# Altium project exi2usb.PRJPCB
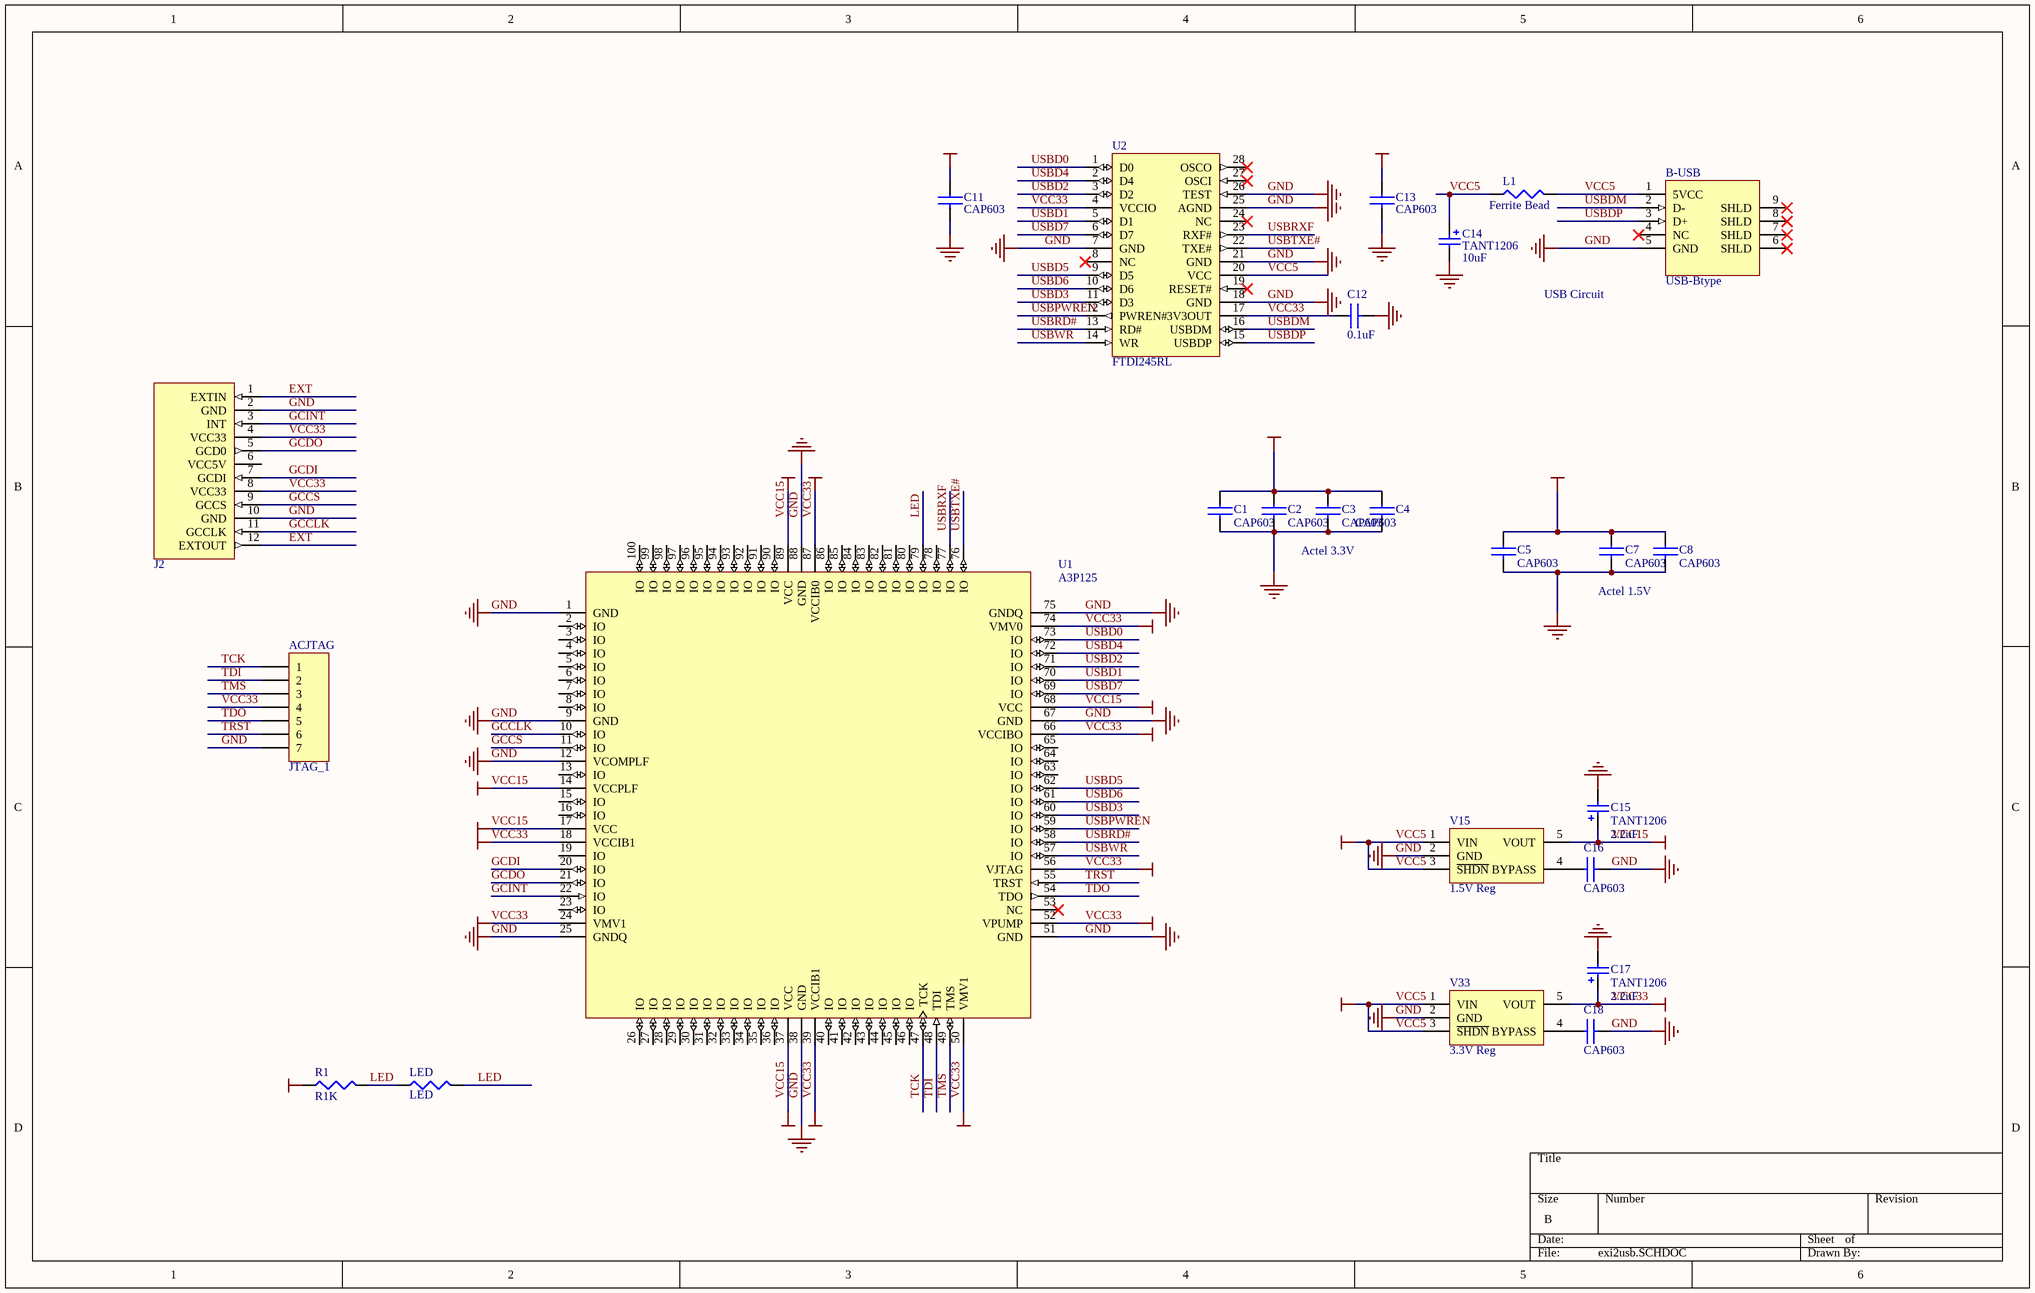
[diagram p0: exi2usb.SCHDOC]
1 sheet, 25 parts. Net scope: global (net labels, ports and power ports of the same name join across sheets).
Board file: exi2usb.PCBDOC

## Sheet exi2usb.SCHDOC
size B

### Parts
ACJTAG  JTAG_1  [ACTJTAG]
B-USB  USB-Btype  [Mini-USB-SMT]
C1  CAP603  [CAP0603]
C2  CAP603  [CAP0603]
C3  CAP603  [CAP0603]
C4  CAP603  [CAP0603]
C5  CAP603  [CAP0603]
C7  CAP603  [CAP0603]
C8  CAP603  [CAP0603]
C11  CAP603  [CAP0603]
C12  0.1uF  [CAP0603]
C13  CAP603  [CAP0603]
C14  TANT1206  value 10uF  [CAP1206]
C15  TANT1206  value 2.2uF  [CAP1206]
C16  CAP603  [CAP0603]
C17  TANT1206  value 2.2uF  [CAP1206]
C18  CAP603  [CAP0603]
J2  GCMEMPADS  [GCMEMPADS]  (value not drawn)
L1  Ferrite Bead  [RES0805]
LED  LED  [RES0805]
R1  R1K  [RES0805]
U1  A3P125  [ACTELVQ100]
U2  FTDI245RL  [SSO-G28/X.4]
V15  1.5V Reg  [SO-G5/P.95]
V33  3.3V Reg  [SO-G5/P.95]

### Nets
GND: ACJTAG.7 B-USB.5(GND) C1.2 C2.2 C3.2 C4.2 C5.2 C7.2 C8.2 C11.2 C12.2 C13.2 C14.2 C15.2 C16.2 C17.2 C18.2 J2.2(GND) J2.10(GND) U1.1(GND) U1.9(GND) U1.12(VCOMPLF) U1.25(GNDQ) U1.38(GND) U1.51(GND) U1.67(GND) U1.75(GNDQ) U1.88(GND) U2.7(GND) U2.18(GND) U2.21(GND) U2.25(AGND) U2.26(TEST) V15.2(GND) V33.2(GND)
VCC5: B-USB.1(5VCC) C13.1 C14.1 L1.1 L1.2 U2.20(VCC) V15.1(VIN) V15.3(~{SHDN}) V33.1(VIN) V33.3(~{SHDN})
VCC15: C5.1 C7.1 C8.1 C15.1 U1.14(VCCPLF) U1.17(VCC) U1.37(VCC) U1.68(VCC) U1.89(VCC) V15.5(VOUT)
VCC33: ACJTAG.4 C1.1 C2.1 C3.1 C4.1 C11.1 C12.1 C17.1 J2.4(VCC33) J2.8(VCC33) R1.1 U1.18(VCCIB1) U1.24(VMV1) U1.39(VCCIB1) U1.50(VMV1) U1.52(VPUMP) U1.56(VJTAG) U1.66(VCCIBO) U1.74(VMV0) U1.87(VCCIB0) U2.4(VCCIO) U2.17(3V3OUT) V33.5(VOUT)
EXT: J2.1(EXTIN) J2.12(EXTOUT)
GCCLK: J2.11(GCCLK) U1.10(IO)
GCCS: J2.9(GCCS) U1.11(IO)
GCDI: J2.7(GCDI) U1.20(IO)
GCDO: J2.5(GCD0) U1.21(IO)
GCINT: J2.3(INT) U1.22(IO)
LED: LED.1 LED.2 R1.2 U1.79(IO)
TCK: ACJTAG.1 U1.47(TCK)
TDI: ACJTAG.2 U1.48(TDI)
TDO: ACJTAG.5 U1.54(TDO)
TMS: ACJTAG.3 U1.49(TMS)
TRST: ACJTAG.6 U1.55(TRST)
USBD0: U1.73(IO) U2.1(D0)
USBD1: U1.70(IO) U2.5(D1)
USBD2: U1.71(IO) U2.3(D2)
USBD3: U1.60(IO) U2.11(D3)
USBD4: U1.72(IO) U2.2(D4)
USBD5: U1.62(IO) U2.9(D5)
USBD6: U1.61(IO) U2.10(D6)
USBD7: U1.69(IO) U2.6(D7)
USBDM: B-USB.2(D-) U2.16(USBDM)
USBDP: B-USB.3(D+) U2.15(USBDP)
USBPWREN: U1.59(IO) U2.12(PWREN#)
USBRD#: U1.58(IO) U2.13(RD#)
USBRXF: U1.77(IO) U2.23(RXF#)
USBTXE#: U1.76(IO) U2.22(TXE#)
USBWR: U1.57(IO) U2.14(WR)
NetC16_1: C16.1 V15.4(BYPASS)
NetC18_1: C18.1 V33.4(BYPASS)

Not connected (* = marked no-connect by the designer): B-USB 4(NC)* 6(SHLD)* 7(SHLD)* 8(SHLD)* 9(SHLD)*; J2 6(VCC5V); U1 2(IO) 3(IO) 4(IO) 5(IO) 6(IO) 7(IO) 8(IO) 13(IO) 15(IO) 16(IO) 19(IO) 23(IO) 26(IO) 27(IO) 28(IO) 29(IO) 30(IO) 31(IO) 32(IO) 33(IO) 34(IO) 35(IO) 36(IO) 40(IO) 41(IO) 42(IO) 43(IO) 44(IO) 45(IO) 46(IO) 53(NC)* 63(IO) 64(IO) 65(IO) 78(IO) 80(IO) 81(IO) 82(IO) 83(IO) 84(IO) 85(IO) 86(IO) 90(IO) 91(IO) 92(IO) 93(IO) 94(IO) 95(IO) 96(IO) 97(IO) 98(IO) 99(IO) 100(IO); U2 8(NC)* 19(RESET#)* 24(NC)* 27(OSCI)* 28(OSCO)*

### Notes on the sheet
- USB Circuit
- Actel 3.3V
- Actel 1.5V

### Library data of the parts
ACJTAG = JTAG_1: Actel Jtag; Manufacturer: Generic Components; Class I: Connector
B-USB = USB-Btype: USB B Type Right Angle, SMT 5 Pin; ContactMaterial: Phosphor Bronze; ContactPlating: Gold (30) over Nickel; PCB_Layout: Complies with manufacturer's recommendation.; DrillSize: Corresponds to nominal value.; PanelGround: Without
C1-C5 C7 C8 C11-C13 C16 C18 = CAP603: Capacitor 603
C14 C15 C17 = TANT1206: Tant 1206 A106 J106; Package Information: Latest Revision: Mar-2001
J2 = GCMEMPADS: Gamecube Memory Card Pads; Manufacturer: DNS; Class I: Connector
L1 LED R1 = RESISTOR805: Resistor 805 Package
U1 = A3P125: Actel Proasic3 A3P125 100 Pin; Manufacturer: Altera; Class I: Programmable Logic Device
U2 = FTDI245RL: FTDI 245RL 28 pin SSOP; Manufacturer: SST; Package Information: Latest Revision: Jun-2006; Class I: Memory; Class II: Flash
V15 V33 = SOT23-5: AIC1733-XXPV; Package Information: Latest Revision: revC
